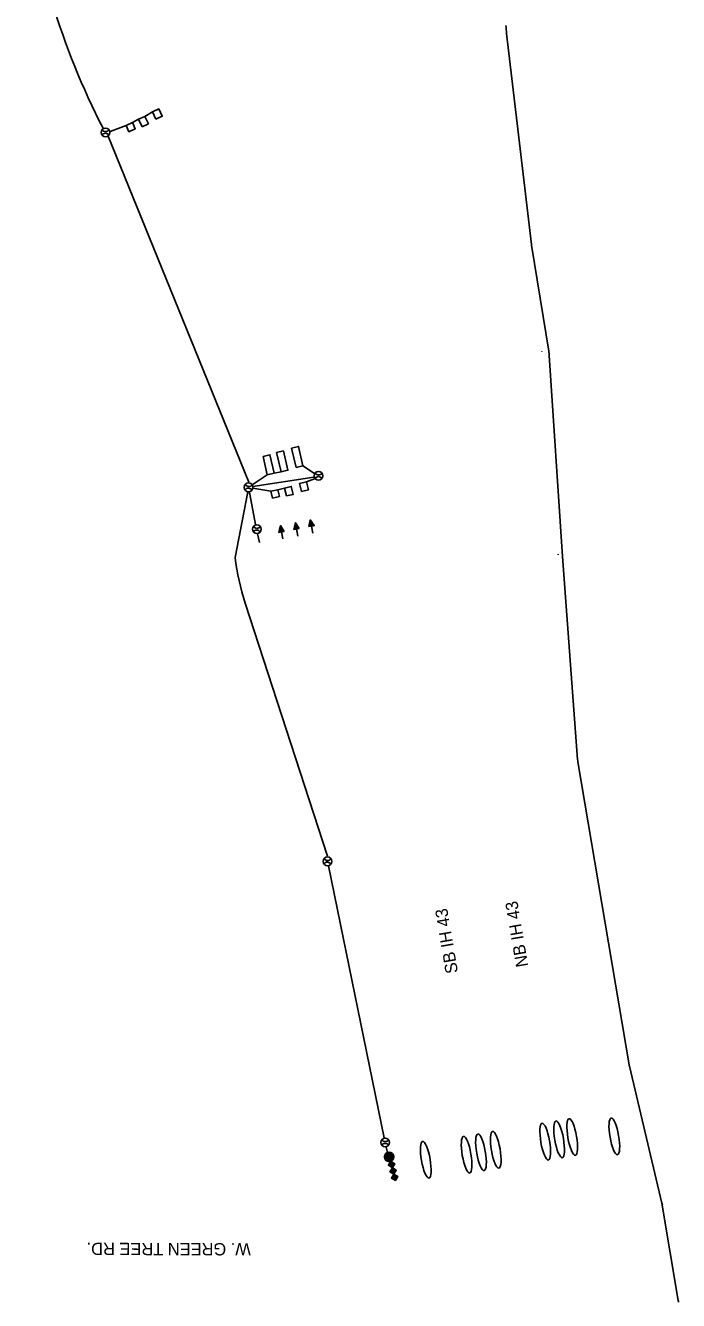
# Model space of a CAD drawing. Extents: x 601562 to 605316, y 332050 to 402250.
# Drawn here: x 604021 to 604579, y 337976 to 339066 of the extents above; entities that cross this region are included whole.
import ezdxf

# ---------------------------------------------------------------- set-up
doc = ezdxf.new("R2010")
doc.units = 0
for name, color, linetype in [('Default', 7, 'Continuous'), ('P_FTMS', 7, 'Continuous'), ('P_FTMSConduit', 7, 'Continuous')]:
    doc.layers.add(name, color=color, linetype=linetype)

# ---------------------------------------------------------------- blocks, each defined once
blk = doc.blocks.new('POINT_DISPLAY')
at = {"layer": 'Default'}
blk.add_line((0, 0), (0, 0), dxfattribs=at)
blk = doc.blocks.new('_U222')
at = {"layer": 'P_FTMS'}
for p, q in [((-4.5, 3.2), (1.5, -0.2)), ((-4.4, 2.8), (1.3, -0.4)), ((-4.3, 3.5), (1.8, 0)), ((-3.9, 3.4), (-4.3, 2.6)), ((-4.3, 2.4), (1, -0.6)), ((-3.5, 3.4), (-4.2, 2.2)), ((-4.2, 2), (0.7, -0.8)), ((-3.2, 3.3), (-4.1, 1.7)), ((-4.1, 1.6), (0.5, -1)), ((-2.9, 3.3), (-4, 1.3)), ((-4, 1.2), (0.2, -1.2)), ((-2.6, 3.2), (-3.9, 0.9)), ((-2.2, 3.2), (-3.8, 0.5)), ((-3.8, 0.7), (0, -1.4)), ((-1.9, 3.2), (-3.7, 0.1)), ((-3.7, 0.3), (-0.3, -1.6)), ((-3.5, 3.4), (2, 0.2)), ((-1.6, 3.1), (-3.5, -0.3)), ((-1.3, 3.1), (-3.4, -0.7)), ((-0.9, 3), (-3.3, -1.2)), ((-0.6, 3), (-3.2, -1.6)), ((-0.3, 2.9), (-3.1, -2)), ((0, 2.9), (-3, -2.4)), ((0.4, 2.8), (-2.9, -2.8)), ((-2.7, 3.3), (2.3, 0.4)), ((0.7, 2.8), (-2.7, -3.2)), ((1, 2.8), (-2.5, -3.4)), ((-1.9, 3.2), (2.5, 0.6)), ((1.3, 2.7), (-1.8, -2.9)), ((1.7, 2.7), (-1.2, -2.3)), ((-1.1, 3), (2.8, 0.8)), ((2, 2.6), (-0.5, -1.8)), ((-0.3, 2.9), (3.1, 1)), ((2.3, 2.6), (0.1, -1.3)), ((0.5, 2.8), (3.3, 1.2)), ((2.6, 2.5), (0.7, -0.8)), ((1.3, 2.7), (3.6, 1.4)), ((3, 2.5), (1.4, -0.3)), ((3.3, 2.4), (2, 0.2)), ((2.2, 2.6), (3.8, 1.6)), ((3.6, 2.4), (2.7, 0.7)), ((3, 2.5), (4.1, 1.8)), ((3.9, 2.3), (3.3, 1.2)), ((3.8, 2.4), (4.3, 2.1)), ((4.3, 2.3), (4, 1.7)), ((-3.6, -0.1), (-0.5, -1.8)), ((-3.5, -0.5), (-0.8, -2)), ((-3.4, -0.9), (-1.1, -2.2)), ((-3.3, -1.3), (-1.3, -2.4)), ((-3.2, -1.7), (-1.6, -2.7)), ((-3, -2.2), (-1.8, -2.9)), ((-2.9, -2.6), (-2.1, -3.1)), ((-2.8, -3), (-2.3, -3.3)), ((-2.7, -3.4), (-2.6, -3.5))]:
    blk.add_line(p, q, dxfattribs=at)
blk.add_lwpolyline([(-4.6, 3.5), (4.6, 2.3), (-2.7, -3.5)], close=True, dxfattribs=at)
blk.add_blockref('POINT_DISPLAY', (4.6, 2.3), dxfattribs=at)
blk = doc.blocks.new('FMD')
at = {"layer": 'P_FTMS'}
for p, q in [((16.9, 17.6), (-16.9, 17.6)), ((-16.1, 16.1), (-16.1, 18.4)), ((16.1, 16.1), (-16.1, 16.1)), ((15.5, 19), (-15.5, 19)), ((-14.6, 14.6), (-14.6, 19.9)), ((14.6, 14.6), (-14.6, 14.6)), ((14, 20.5), (-14, 20.5)), ((-13.2, 13.2), (-13.2, 21.3)), ((13.2, 13.2), (-13.2, 13.2)), ((12.5, 21.9), (-12.5, 21.9)), ((-11.7, 11.7), (-11.7, 22.8)), ((11.7, 11.7), (-11.7, 11.7)), ((11.1, 23.4), (-11.1, 23.4)), ((-10.2, 10.2), (-10.2, 24.2)), ((10.2, 10.2), (-10.2, 10.2)), ((9.6, 24.9), (-9.6, 24.9)), ((-8.8, 8.8), (-8.8, 25.7)), ((8.8, 8.8), (-8.8, 8.8)), ((8.2, 26.3), (-8.2, 26.3)), ((-7.3, 7.3), (-7.3, 27.2)), ((7.3, 7.3), (-7.3, 7.3)), ((6.7, 27.8), (-6.7, 27.8)), ((-5.9, 5.9), (-5.9, 28.6)), ((5.9, 5.9), (-5.9, 5.9)), ((5.2, 29.3), (-5.2, 29.3)), ((-4.4, 4.4), (-4.4, 30.1)), ((4.4, 4.4), (-4.4, 4.4)), ((3.8, 30.7), (-3.8, 30.7)), ((-2.9, 2.9), (-2.9, 31.6)), ((2.9, 2.9), (-2.9, 2.9)), ((2.3, 32.2), (-2.3, 32.2)), ((-1.5, 1.5), (-1.5, 33)), ((1.5, 1.5), (-1.5, 1.5)), ((0.8, 33.6), (-0.8, 33.6)), ((0, 0), (0, 34.5)), ((1.5, 1.5), (1.5, 33)), ((2.9, 2.9), (2.9, 31.6)), ((4.4, 4.4), (4.4, 30.1)), ((5.9, 5.9), (5.9, 28.6)), ((7.3, 7.3), (7.3, 27.2)), ((8.8, 8.8), (8.8, 25.7)), ((10.2, 10.2), (10.2, 24.2)), ((11.7, 11.7), (11.7, 22.8)), ((13.2, 13.2), (13.2, 21.3)), ((14.6, 14.6), (14.6, 19.9)), ((16.1, 16.1), (16.1, 18.4))]:
    blk.add_line(p, q, dxfattribs=at)
blk.add_lwpolyline([(-17.2, 17.2), (0, 34.5), (17.2, 17.2), (0, 0)], close=True, dxfattribs=at)

msp = doc.modelspace()

# ---------------------------------------------------------------- linework, layer by layer
at = {"layer": 'P_FTMS'}
for p, q in [((604117.8, 338985.8), (604112.5, 338983.2)), ((604129.7, 338992.2), (604123.2, 338988.3)), ((604107.1, 338980.6), (604093.4, 338975.5)), ((604227.9, 338682), (604214.9, 338673.4)), ((604239.6, 338684.5), (604233.8, 338683.4)), ((604258.4, 338689.6), (604268.3, 338683.1)), ((604231, 338667.8), (604215.5, 338670.4)), ((604242.6, 338670.6), (604236.8, 338669.2)), ((604261.4, 338675.8), (604268.3, 338678.6)), ((604254.1, 338629.6), (604252.9, 338635.6)), ((604266.9, 338632), (604265.8, 338638.1)), ((604241.3, 338627.1), (604240.1, 338633.1)), ((604328.1, 338099.6), (604334.4, 338102)), ((604328.1, 338099.4), (604334.6, 338101.9)), ((604328.1, 338099.1), (604334.8, 338101.7)), ((604328.1, 338098.8), (604335, 338101.5)), ((604328.2, 338099.9), (604334.2, 338102.2)), ((604328.3, 338100.2), (604333.9, 338102.4)), ((604328.4, 338100.5), (604333.6, 338102.5)), ((604328.6, 338100.8), (604333.2, 338102.6)), ((604328.8, 338101.2), (604332.8, 338102.7)), ((604331.5, 338094.9), (604329, 338101.4)), ((604329.2, 338101.6), (604332.4, 338102.8)), ((604331.8, 338094.8), (604329.2, 338101.6)), ((604332, 338094.8), (604329.4, 338101.8)), ((604332.3, 338094.8), (604329.6, 338101.9)), ((604329.7, 338102), (604331.7, 338102.8)), ((604332.5, 338094.9), (604329.8, 338102.1)), ((604332.8, 338094.9), (604330, 338102.2)), ((604333, 338095), (604330.2, 338102.3)), ((604333.3, 338095), (604330.4, 338102.5)), ((604333.5, 338095.1), (604330.6, 338102.5)), ((604333.7, 338095.2), (604330.8, 338102.6)), ((604333.9, 338095.3), (604331.1, 338102.7)), ((604334.1, 338095.4), (604331.3, 338102.7)), ((604334.3, 338095.6), (604331.6, 338102.8)), ((604334.5, 338095.7), (604331.8, 338102.8)), ((604334.7, 338095.9), (604332.1, 338102.8)), ((604334.9, 338096.1), (604332.3, 338102.8)), ((604335.1, 338096.2), (604332.6, 338102.8)), ((604335.3, 338096.5), (604332.9, 338102.7)), ((604335.4, 338096.7), (604333.1, 338102.7)), ((604335.6, 338097), (604333.4, 338102.6)), ((604335.7, 338097.3), (604333.7, 338102.4)), ((604335.9, 338097.6), (604334.1, 338102.3)), ((604336, 338098), (604334.4, 338102)), ((604336, 338098.5), (604334.8, 338101.7)), ((604328.1, 338098.6), (604335.2, 338101.3)), ((604328.1, 338098.3), (604335.3, 338101.1)), ((604328.1, 338098.1), (604335.4, 338100.9)), ((604329.7, 338095.6), (604328.1, 338099.6)), ((604329.3, 338095.9), (604328.1, 338099.1)), ((604328.9, 338096.4), (604328.1, 338098.5)), ((604328.2, 338097.8), (604335.6, 338100.7)), ((604330, 338095.4), (604328.2, 338100)), ((604328.3, 338097.6), (604335.7, 338100.5)), ((604328.3, 338097.4), (604335.8, 338100.3)), ((604330.4, 338095.2), (604328.4, 338100.4)), ((604328.4, 338097.2), (604335.9, 338100)), ((604330.7, 338095.1), (604328.5, 338100.7)), ((604328.5, 338097), (604335.9, 338099.8)), ((604328.6, 338096.7), (604336, 338099.6)), ((604331, 338095), (604328.7, 338100.9)), ((604331.2, 338094.9), (604328.8, 338101.2)), ((604328.8, 338096.5), (604336, 338099.3)), ((604328.9, 338096.3), (604336, 338099.1)), ((604329.1, 338096.1), (604336, 338098.8)), ((604329.3, 338096), (604336, 338098.6)), ((604329.5, 338095.8), (604336, 338098.3)), ((604329.7, 338095.6), (604336, 338098)), ((604329.9, 338095.4), (604335.9, 338097.7)), ((604330.2, 338095.3), (604335.8, 338097.4)), ((604330.5, 338095.1), (604335.7, 338097.1)), ((604330.8, 338095), (604335.5, 338096.8)), ((604331.3, 338094.9), (604335.3, 338096.5)), ((604331.7, 338094.9), (604334.9, 338096.1)), ((604332.4, 338094.9), (604334.4, 338095.6)), ((604336, 338099.2), (604335.2, 338101.2))]:
    msp.add_line(p, q, dxfattribs=at)
for points in [[(604120.8, 338979.4), (604117.8, 338985.8), (604117.8, 338985.8), (604123.2, 338988.3), (604126.2, 338982), (604120.8, 338979.4)], [(604132.7, 338985.8), (604129.7, 338992.2), (604129.7, 338992.2), (604135.1, 338994.7), (604138.1, 338988.4), (604132.7, 338985.8)], [(604107.1, 338980.6), (604112.5, 338983.2), (604115, 338977.7), (604109.6, 338975.2), (604107.1, 338980.6)], [(604235.8, 338701), (604241.6, 338702.4), (604245.5, 338685.8), (604239.6, 338684.5), (604239.6, 338684.5), (604235.8, 338701)], [(604248.7, 338704.8), (604254.6, 338706.2), (604258.4, 338689.6), (604252.6, 338688.2), (604252.6, 338688.2), (604248.7, 338704.8)], [(604224.3, 338697.6), (604230.1, 338699), (604233.8, 338683.4), (604227.9, 338682), (604224.3, 338697.6)], [(604231, 338667.8), (604236.8, 338669.2), (604238.2, 338663.4), (604232.4, 338662), (604231, 338667.8)], [(604244.2, 338663.8), (604242.6, 338670.6), (604242.6, 338670.6), (604248.4, 338672), (604250, 338665.2), (604244.2, 338663.8)], [(604257.1, 338667.6), (604255.5, 338674.4), (604255.5, 338674.4), (604261.4, 338675.8), (604263, 338669), (604257.1, 338667.6)]]:
    msp.add_lwpolyline(points, dxfattribs=at)
for centre, radius in [((604089.5, 338974.6), 3.75), ((604271.7, 338681.1), 3.75), ((604211.9, 338671.2), 3.75), ((604219, 338635.4), 3.75), ((604279.4, 338351.5), 3.75), ((604328.7, 338111.2), 3.75), ((604332, 338098.8), 4)]:
    msp.add_circle(centre, radius, dxfattribs=at)
for centre, start, end in [((604089.5, 338979.1), 216.2095, 322.4651), ((604089.4, 338970.1), 36.2095, 142.4651), ((604271.6, 338676.6), 34.9457, 141.2014), ((604271.9, 338685.6), 214.9457, 321.2014), ((604211.8, 338666.7), 34.9457, 141.2014), ((604212.1, 338675.7), 214.9457, 321.2014), ((604219.2, 338639.9), 214.1999, 320.4555), ((604218.8, 338630.9), 34.1999, 140.4555), ((604279.4, 338356), 216.2095, 322.4651), ((604279.3, 338347), 36.2095, 142.4651), ((604328.8, 338115.7), 216.2095, 322.4651), ((604328.7, 338106.7), 36.2095, 142.4651)]:
    msp.add_arc(centre, 3.75, start, end, dxfattribs=at)
for centre in [(604465.5, 338111.9), (604477.4, 338113.9), (604488.6, 338115.8), (604524.6, 338116.4), (604363.4, 338096.4), (604398.3, 338100.7), (604410.6, 338102.8), (604423.2, 338105)]:
    msp.add_ellipse(centre, major_axis=(-2.7, 15.7), ratio=0.23471, dxfattribs=at)
at = {"layer": 'P_FTMSConduit'}
for p, q in [((604453.8, 338878.7), (604432.5, 339059.2)), ((604212.1, 338675.7), (604091.9, 338971.5)), ((604468.6, 338787.6), (604453.9, 338878.1)), ((604480.2, 338612.1), (604468.5, 338788.2)), ((604215.5, 338671.9), (604267.7, 338680)), ((604211.2, 338667.5), (604200.4, 338611.2)), ((604221.2, 338624.1), (604219.4, 338631.4)), ((604493.2, 338438.5), (604480.2, 338612.1)), ((604208.9, 338572.2), (604279.4, 338356)), ((604537.2, 338177.5), (604493.4, 338436.7)), ((604327.8, 338115.1), (604280.3, 338347.6)), ((604565.3, 338059.3), (604537.5, 338176.3)), ((604329.6, 338107.3), (604330.6, 338102.6)), ((604579.3, 337976.1), (604565.6, 338057.6))]:
    msp.add_line(p, q, dxfattribs=at)
for points in [[(604212.5, 338667.4), (604212.6, 338666.7)], [(604217.9, 338639.3), (604212.9, 338665.3)]]:
    msp.add_lwpolyline(points, dxfattribs=at)
for centre, radius, start, end in [((604640.3, 339264.4), 622.5, 185.958, 207.3838), ((604531.8, 339070.9), 100, 182.8212, 186.7354), ((604429, 338875.8), 25, 5.4088, 6.7354), ((604437.6, 338785.1), 25, 4.6524, 5.4088), ((604286.5, 338679.7), 75, 189.4195, 191.0696), ((604501.5, 338616), 25, 184.6524, 185.4069), ((604399.1, 338634.2), 200, 186.6238, 198.0562), ((604518.1, 338440.8), 25, 185.4069, 189.5962), ((604561.8, 338182.1), 25, 189.5962, 193.3521), ((604541, 338053.5), 25, 9.5069, 13.3521), ((604554.6, 337972), 25, 5.9108, 9.5069)]:
    msp.add_arc(centre, radius, start, end, dxfattribs=at)

# ---------------------------------------------------------------- block references
at = {"layer": 'P_FTMS'}
for name, p, xscale, yscale, rotation in [('_U222', (604239.1, 338635.2), 0.6330710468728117, -0.6330710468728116, 116.25578027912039), ('_U222', (604251.9, 338637.7), 0.6330710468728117, -0.6330710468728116, 116.25578027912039), ('_U222', (604265.9, 338640.4), 0.6330710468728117, 0.6330710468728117, 85.60583638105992), ('FMD', (604336.9, 338093), 0.16404166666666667, 0.1640416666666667, 103.08542551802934), ('FMD', (604338.2, 338087.5), 0.16404166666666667, 0.1640416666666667, 103.08542551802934), ('FMD', (604339.5, 338082), 0.16404166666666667, 0.1640416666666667, 103.08542551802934)]:
    msp.add_blockref(name, p, dxfattribs=dict(at, xscale=xscale, yscale=yscale, rotation=rotation))

# ---------------------------------------------------------------- texts
at = {"layer": 'P_FTMSConduit'}
for s, rotation, p in [('SB IH 43', 99.637, (604391, 338256.5)), ('NB IH 43', 99.637, (604451.1, 338262)), ('W. GREEN TREE RD.', 179.8354, (604213.8, 338025.1))]:
    msp.add_text(s, height=10.5, rotation=rotation, dxfattribs=at).set_placement(p)

doc.saveas('drawing.dxf')
